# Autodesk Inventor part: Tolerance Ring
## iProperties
Author: Stephan
Shininess: 64.0
Angle Display Precision: 2
Document Length Units: 11269
Document Angle Units: 11286
Document Time Units: 11279
Document Mass Units: 11290
Document Length Units Precision: 3
Document Angle Units Precision: 2
Compacted: False
PropertySet Name: _Private Model Information
Created: 2006-11
Part Number: Tolerance Ring
Document SubType Name: Modeling
Designer: Stephan
Control State: 0
Master: False
Checked Out: False
PropertySet Name: Design Tracking Control
Density: 0.0
Volumn: 0.0
Area: 0.0
PropertySet Name: Model Information
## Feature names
1. Extrusion2
2. Extrusion1
3. Fillet1
4. Extrusion3
5. Fillet2
6. Circular Pattern1
7. Shell1
